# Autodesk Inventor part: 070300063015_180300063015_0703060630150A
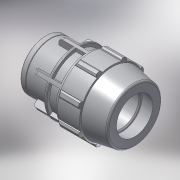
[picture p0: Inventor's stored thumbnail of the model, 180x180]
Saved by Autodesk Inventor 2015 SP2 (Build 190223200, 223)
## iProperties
Created: 2017-02
Part Number: 070300063015_180300063015_0703060630150A
Material: PVC-Piping
Description: PLASSON FEMALE ADAPTOR 63-1.1/2"
Document SubType Name: Modeling
Designer: KIM
Mass: 92.6774 g
Surface Area: 199.44 cm^2
Volume: 66.1981 cm^3
Density: 1.4 g/cm^3
Appearance: Smooth - White
Author: KIM
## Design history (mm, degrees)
derived "07030.ipt"
feature "Solid1::07030.ipt"
tag "TaggingFeature1"
body "Solid1"
other parameters: "d2" = 63, "d4" = 19.85714, "d5" = 34.75, "d7" = 113, "d9" = 19.85714, "d11" = 3.97143, "d12" = 90.4, "d13" = 120 deg, "d14" = 88.2, "d15" = 10 deg, "d16" = 101.7, "d18" = 3.15, "d19" = 35 deg, "d20" = 17.5 deg, "d21" = 105.09, "d23" = 0, "d25" = 360 deg, "d27" = 2.26, "d34" = 5.65, "d35" = 41.7, "d36" = 0, "d42" = 34.75, "d43" = 3.39, "d46" = 1.89, "d51" = 139, "d53" = 1.26, "d55" = 360 deg, "d61" = 25, "d62" = 50.4, "d63" = 44.845, "d64" = 46.33333, "d65" = 5.65, "d66" = 0.5, "d67" = 1, "d68" = 7.5, "d69" = 81.36, "d70" = 2.825, "d_" = 63, "E_" = 113, "H_" = 139, "l_2" = 25, "Rp_" = 44.845
